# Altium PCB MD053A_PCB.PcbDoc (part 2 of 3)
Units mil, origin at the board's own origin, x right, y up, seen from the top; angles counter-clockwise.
Board outline 3650 x 5180 mil, 4 copper layers (Top Layer, GND Layer, Power Layer, Bottom Layer), stack 58.4 mil thick; 251 components, 138 nets, 532 pads, 1017 vias.
Unrouted connection lines stored in the file: 42.
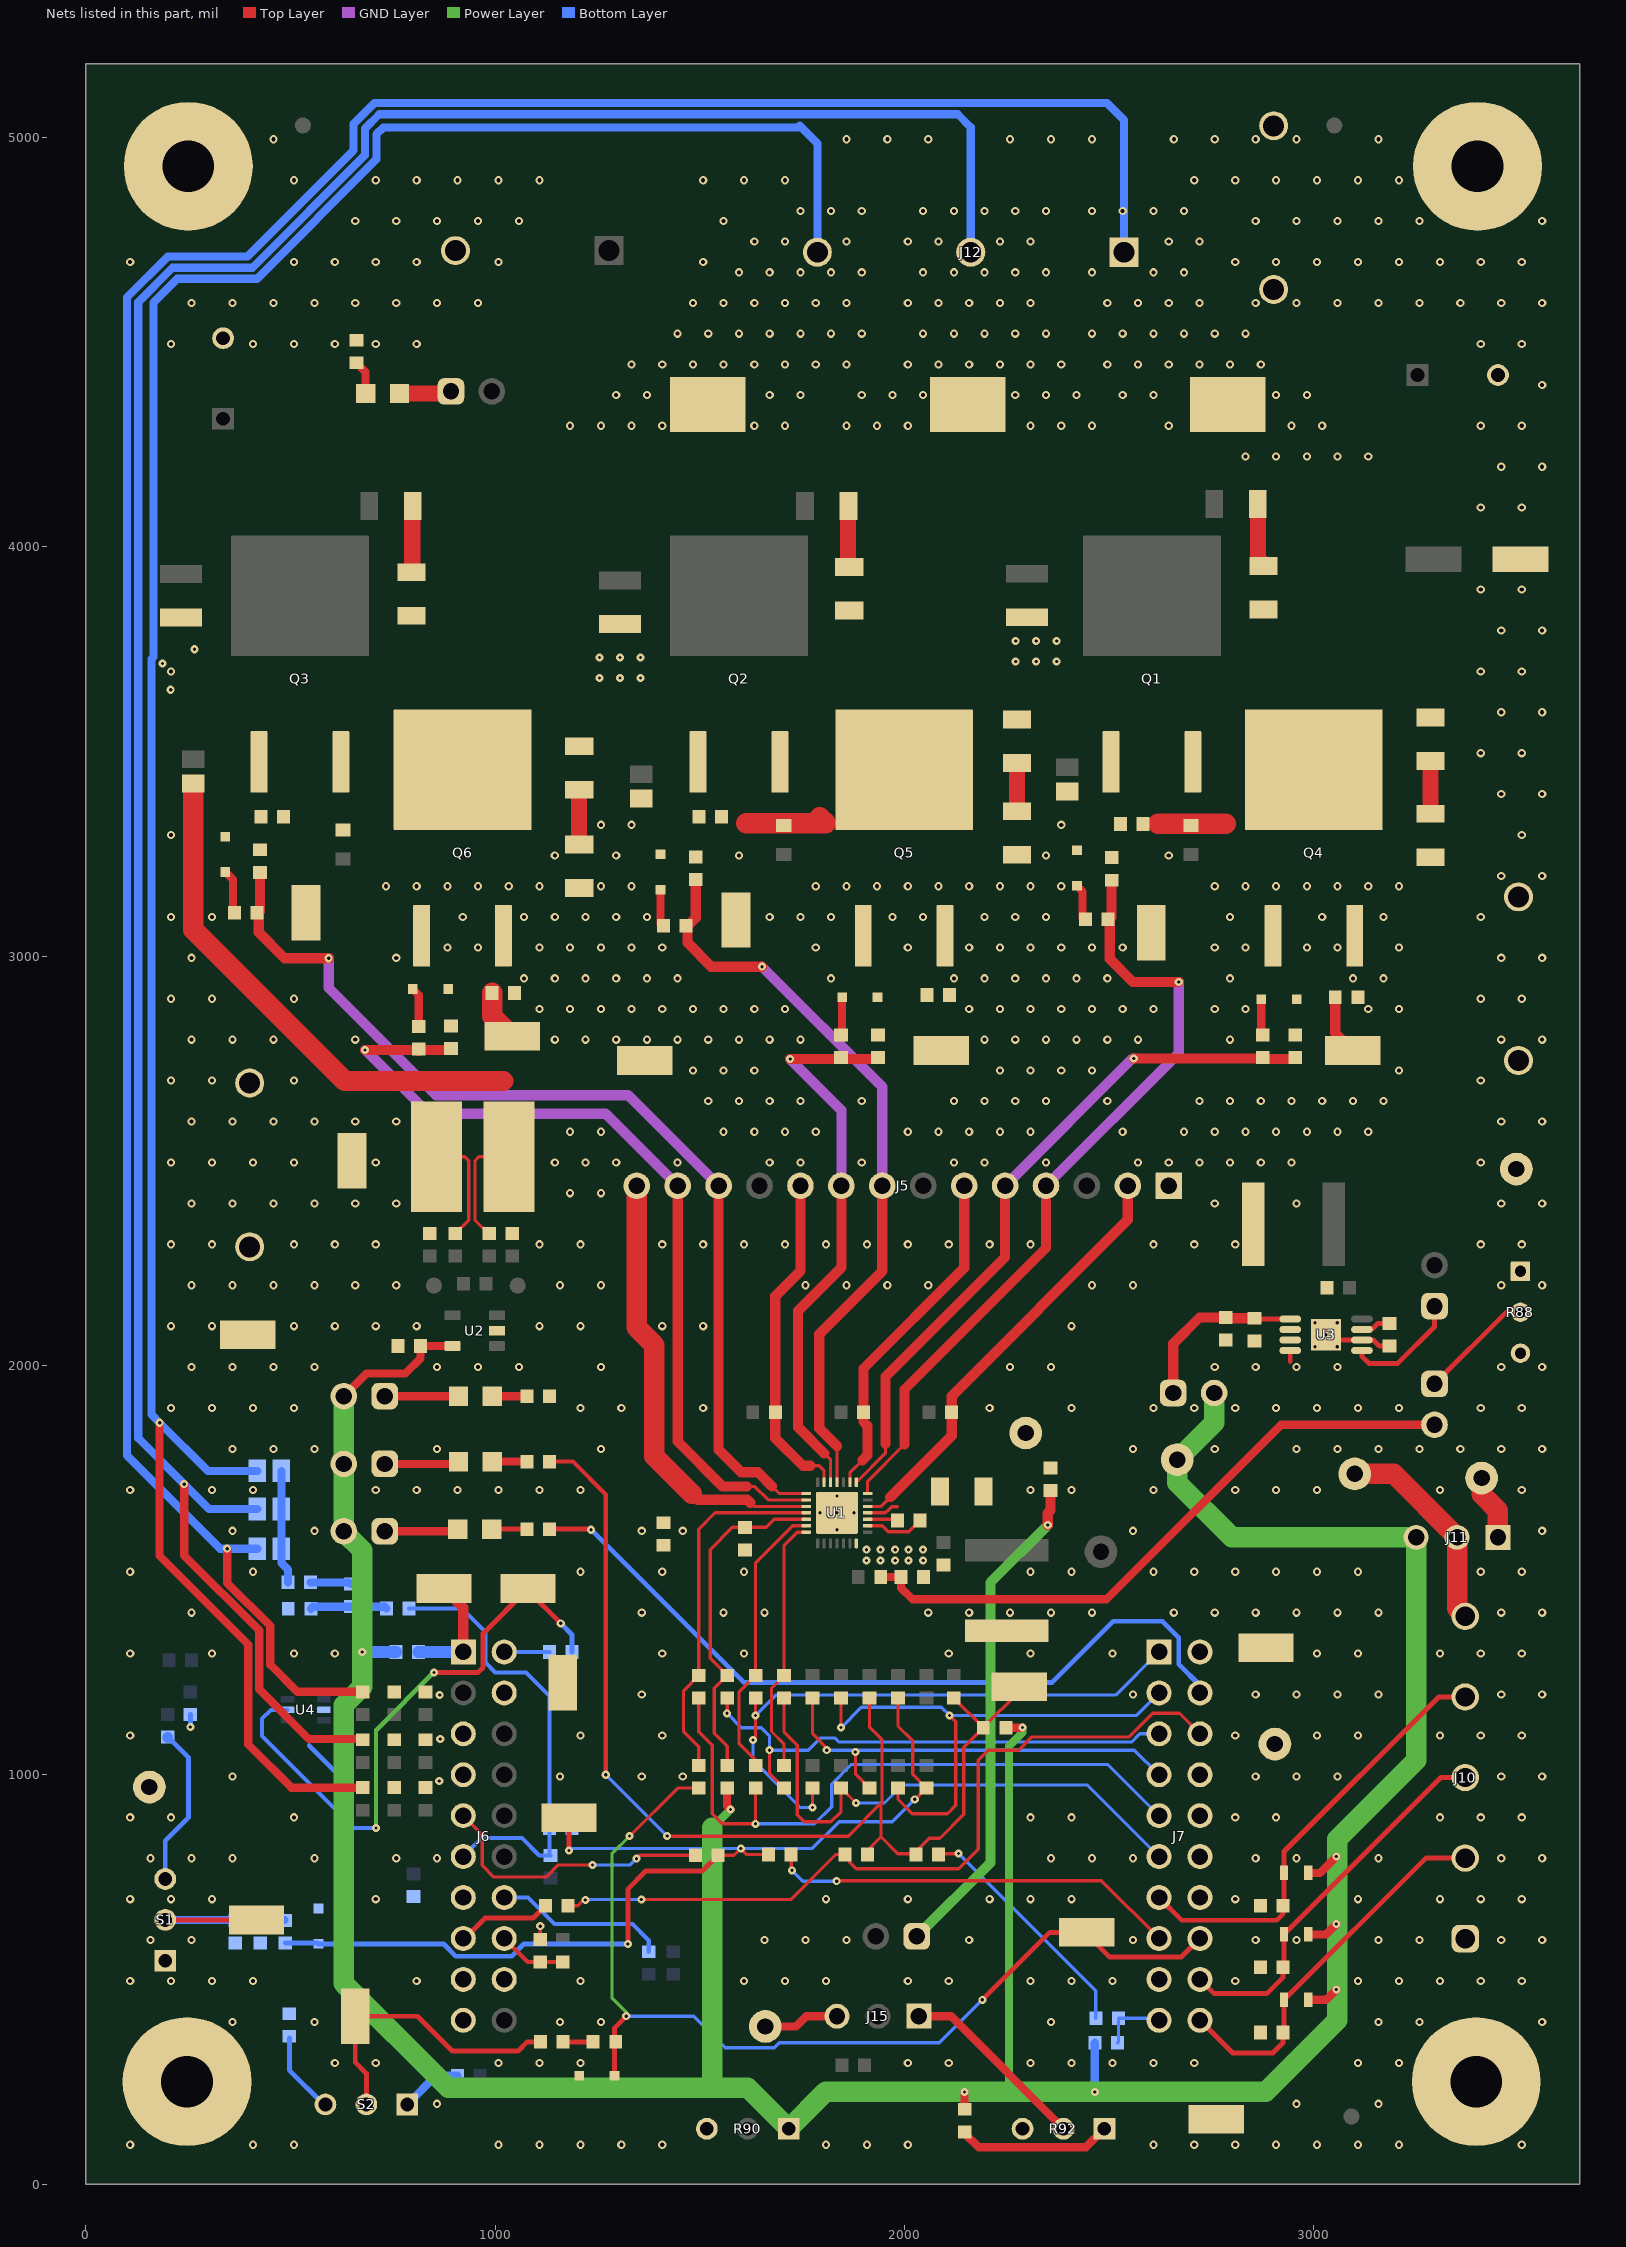
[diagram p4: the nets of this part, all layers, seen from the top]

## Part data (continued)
C6: library part CMP-0007424-3, "CAP, CERM, 0.47 uF, 25 V, +/- 10%, X7R, 0603", Cap_Case=0603, Manufacturer=MuRata, Supplier Part Number 1=490-3291-1-ND, TempCo=X7R, Tolerance_%=10%, Value1=Unknown, Value2=25V, ValueDisplayed=0.47uF
C7: library part CMP-0086153-1, "CAP, CERM, 10 µF, 50 V,+/- 10%, X5R, 1206", Cap_Case=1206, Manufacturer="Taiyo Yuden", TempCo=X5R, Tolerance_%=10%, Value2=50V, ValueDisplayed=10µF
C10 C11 C12 C22 C23 C24: library part CMP-0008756-2, "CAP CER 3900PF 100V X7R 1206", Cap_Case=1206, Manufacturer="AVX Corporation", Supplier Part Number 1=478-6364-1-ND, TempCo=X7R, Tolerance_%=10%, Value1=Unknown, Value2=100V, ValueDisplayed=3900pF
C13 C15 C17 C25 C26 C27 C37: library part CMP-0007441-5, "CAP, CERM, 2000 pF, 50 V, +/- 10%, X7R, 0603", Cap_Case=0603, Manufacturer=MuRata, TempCo=X7R, Tolerance_%=10%, Value1=Unknown, Value2=50V, ValueDisplayed=2000pF
C14 C16 C18: library part CMP-0009084-1, "CAP, CERM, 2.2 uF, 100 V, +/- 10%, X7R, 1210", Cap_Case=1210, Manufacturer=Kemet, Supplier Part Number 1=399-5511-2-ND, TempCo=X7R, Tolerance_%=10%, Value1=Unknown, Value2=100V, ValueDisplayed=2.2uF
C19 C20 C21: library part CMP-0007542-2, "CAP, CERM, 0.01 uF, 100 V, +/- 5%, X7R, 0805", Cap_Case=0805, Manufacturer=AVX, Supplier Part Number 1=478-3745-1-ND, TempCo=X7R, Tolerance_%=5%, Value1="0.078 ohm", Value2=100V, ValueDisplayed=0.01uF
C28 C32: library part CMP-0006740-4, "CAP, CERM, 330 pF, 100 V, +/- 10%, X7R, 0603", Cap_Case=0603, Manufacturer=AVX, Supplier Part Number 1=478-1196-1-ND, TempCo=X7R, Tolerance_%=10%, Value1="0.472 ohm", Value2=100V, ValueDisplayed=330pF
C29: library part CMP-0006857-4, "CAP, CERM, 0.1 uF, 16 V, +/- 5%, X7R, 0603", Cap_Case=0603, Manufacturer=Kemet, Supplier Part Number 1=399-1097-1-ND, TempCo=X7R, Tolerance_%=5%, Value1=Unknown, Value2=16V, ValueDisplayed=0.1uF
C30: library part CMP-0006998-4, "CAP, CERM, 0.01 uF, 50 V, +/- 5%, C0G/NP0, 0603", Cap_Case=0603, Manufacturer=TDK, Supplier Part Number 1=445-14056-1-ND, TempCo=C0G/NP0, Tolerance_%=5%, Value1=Unknown, Value2=50V, ValueDisplayed=0.01uF
C31: library part CMP-0007387-4, "CAP, CERM, 2200 pF, 16 V, +/- 10%, X7R, 0603", Cap_Case=0603, Manufacturer=MuRata, Supplier Part Number 1=GRM188R71C222KA01D-ND, TempCo=X7R, Tolerance_%=10%, Value1=Unknown, Value2=16V, ValueDisplayed=2200pF
C35: library part CMP-0006872-5, "CAP, CERM, 10 uF, 6.3 V, +/- 20%, X5R, 0603", Cap_Case=0603, Manufacturer=Kemet, Supplier Part Number 1=399-5504-1-ND, TempCo=X5R, Tolerance_%=20%, Value1="0.004 ohm", Value2=6.3V, ValueDisplayed=10uF
C36: library part CMP-0007475-4, "CAP, CERM, 2200 pF, 100 V, +/- 10%, X7R, 0603", Cap_Case=0603, Manufacturer=MuRata, Supplier Part Number 1=490-1478-1-ND, TempCo=X7R, Tolerance_%=10%, Value1=Unknown, Value2=100V, ValueDisplayed=2200pF
C38: library part CMP-0011397-2, "CAP, AL, 10 uF, 80 V, +/- 20%, 2.4 ohm, SMD", Cap_Case=F80, Manufacturer=Chemi-Con, Tolerance_%=20%, Value1="2.4 ohm", Value2=80V, ValueDisplayed=10uF
C39 C40: library part CMP-0009875-2, "CAP, AL, 390 uF, 100 V, +/- 20%, 0.026 ohm, TH", Cap_Case=12.5x35mm, Manufacturer=Chemi-Con, Supplier Part Number 1=565-4021-ND, Tolerance_%=20%, Value1="0.026 ohm", Value2=100V, ValueDisplayed=390uF
C41 C45 C46 C47: library part CMP-0083854-1, "CAP, CERM, 0.1 µF, 50 V,+/- 5%, X7R, 0603", Cap_Case=0603, Manufacturer=AVX, TempCo=X7R, Tolerance_%=5%, Value2=50V, ValueDisplayed=0.1µF
C42 C43 C44: library part CMP-0006826-4, "CAP, CERM, 1000 pF, 16 V, +/- 10%, X7R, 0603", Cap_Case=0603, Manufacturer="Wurth Elektronik", Supplier Part Number 1=710-885012206034, TempCo=X7R, Tolerance_%=10%, Value1=Unknown, Value2=16V, ValueDisplayed=1000pF
C48: library part CMP-0006811-4, "CAP, CERM, 10 pF, 10 V, +/- 10%, X7R, 0603", Cap_Case=0603, Manufacturer=AVX, Supplier Part Number 1=0603ZC100KAT2A-ND, TempCo=X7R, Tolerance_%=10%, Value1=Unknown, Value2=10V, ValueDisplayed=10pF
D1 D3: library part CMP-0002888-2, "LED, Green, SMD", Color=Green, Manufacturer=Lite-On, Value1=W, Value2=2V
D2: library part CMP-0002829-3, "LED, Red, SMD", Color=red, Manufacturer=Lite-On, Value1=W, Value2=2V
D4: library part CMP-0002890-1, "LED, Orange, SMD", Color=orange, Manufacturer=Lite-On, Supplier Part Number 1=160-1413-1-ND, Value1=W, Value2=2V
D5 D6 D7 D8 D9 D10: library part CMP-0076911-2, "Diode, Switching, 75 V, 0.25 A, SOD-323", Manufacturer="Micro Commercial Components", Value1=0.25A, Value2=V
D11 D12: library part CMP-0085730-1, "Diode, Zener, 3.3 V, 300 mW, AEC-Q101, SOD-323", Manufacturer="ON Semiconductor", Power_W=300mW, Value1=0.3W
FID1 FID2 FID3: library part CMP-0077181-1, "Fiducial mark.  There is nothing to buy or mount.", Manufacturer=N/A
H1 H2 H3 H4: library part CMP-0003617-1, "Machine Screw, Round, #4-40 x 1/4, Nylon, Philips panhead", Manufacturer="B&F Fastener Supply", Supplier Part Number 1=H542-ND
H5 H6 H7 H8: library part CMP-0003610-1, "Standoff, Hex, 0.5\"L #4-40 Nylon", Manufacturer=Keystone, Supplier Part Number 1=36-1902C-ND
J1 J2 J3 J4 J14: library part CMP-0075405-3, "Header, 100mil, 2x1, Gold, TH", Color=Black, Current_A=6.3A, Manufacturer=Samtec, Supplier Part Number 1=SAM1029-02-ND, Voltage_V=550V
J5: library part CMP-0075428-1, "Header, 100mil, 14x1, Gold, TH", Color=Black, Current_A=6.3A, Manufacturer=Samtec, Supplier Part Number 1=SAM1029-14-ND, Voltage_V=550V
J6 J7: library part CMP-0075613-1, "Receptacle, 2.54mm, 10x2, Gold, TH", Color=Black, Current_A=6.3A, Manufacturer=Samtec, Voltage_V=550V
J8 J13 J16: library part CMP-0075405-3, "Header, 100mil, 2x1, Gold, TH", Color=Black, Current_A=6.3A, Manufacturer=Samtec, PartNumber=TSW-102-07-G-S, Supplier Part Number 1=SAM1029-02-ND, Voltage_V=550V
J9: library part CMP-0055527-1, "Terminal Block, 9.52mm, 2x1, R/A, TH", Color=Green, Current_A=32A, Manufacturer="Phoenix Contact", PartNumber=1902547, Supplier Part Number 1=277-5951-ND, Voltage_V=1kV
J10: library part CMP-0055532-1, "Terminal Block, 5mm, 5x1, R/A, TH", Color=Green, Current_A=16A, Manufacturer="Phoenix Contact", PartNumber=1792892, Supplier Part Number 1=277-2521-ND, Voltage_V=400V
J11 J15: library part CMP-0065026-1, "Header, 2.54mm, 3x1, Tin, TH", Color=Black, Current_A=3A, Manufacturer=FCI, PartNumber=68001-403HLF, Supplier Part Number 1=609-3471-ND, Voltage_V=1.5kV
J12: library part CMP-0055528-1, "Terminal Block, 9.52mm, 3x1, R/A, TH", Color=Green, Current_A=32A, Manufacturer="Phoenix Contact", PartNumber=1904150, Supplier Part Number 1=277-6184-ND, Voltage_V=1kV
LBL1: library part CMP-0003625-1, "Thermal Transfer Printable Labels, 0.650\" W x 0.200\" H - 10,000 per roll", Manufacturer=Brady, Supplier Part Number 1=97C5133
Logo1: library part CMP-0074844-1
Logo2: library part CMP-0074838-1, "Texas Instrument Corporate Signature"
Logo3: library part CMP-0074847-1, "FCC_disclaimer"
Logo4: library part CMP-0074769-1
LOGO5 LOGO6 LOGO7: library part CMP-0074837-1, "IEC 61010-1 Hot Surface Warning"
NT1 NT2 NT3: library part CMP-0078142-2, "Single point connection between nets.", Manufacturer=N/A
Q1 Q2 Q3 Q4 Q5 Q6: library part CMP-0092295-1, "MOSFET 60-V, N channel NexFET power MOSFET, single D2PAK, 1.6 mOhm 3-DDPAK/TO-263 -55 to 175", Digikey Part Number=296-44122-1-ND, Drain To Source Breakdown Voltage=60V, Input Capacitace At Vds="8790pF @ 30V", Manufacturer="Texas Instruments", Mouser Part Number=595-CSD18536KTTT, Operating Temperature Range="-55°C to +175°C", Power_W=375W, Pulse Drain Current=400A, Typ Forward Diode Voltage=0.9V
R1 R2 R3 R4 R5 R6 R7 R8 R9 R10 R11 R12 R13 R14 R15 R17 R18 R19 R20 R21 R26 R27 R28 R29 R30 R31 R32 R33 R34 R35 R36 R38 R39 R58 R61 R75 R76 R80 R81 R85: library part CMP-0025874-4, "RES, 0, 5%, 0.1 W, AEC-Q200 Grade 0, 0603", Manufacturer=Panasonic, Power_W=100mW, Supplier Part Number 1=P0.0GCT-ND, TempCo="600 ppm/C", Tolerance_%=5%, Value2=0.1W, Value_Code=0000, ValueDisplayed=0
R16: library part CMP-0025830-4, "RES, 5.1 k, 5%, 0.1 W, AEC-Q200 Grade 0, 0603", Manufacturer=Vishay-Dale, Power_W=100mW, Supplier Part Number 1=541-5.1KGCT-ND, TempCo="200 ppm/C", Tolerance_%=5%, Value2=0.1W, Value_Code=5k10, ValueDisplayed=5.1k
R22 R23 R25: library part CMP-0025941-5, "RES, 820, 5%, 0.1 W, 0603", Manufacturer=Yageo, Power_W=100mW, Supplier Part Number 1=311-820GRCT-ND, TempCo="100 ppm/C", Tolerance_%=5%, Value2=0.1W, Value_Code=820R, ValueDisplayed=820
R24: library part CMP-0023463-3, "RES, 2.00 k, 0.1%, 0.1 W, 0603", Manufacturer="Susumu Co Ltd", Power_W=100mW, Supplier Part Number 1=RG16P2.0KBCT-ND, TempCo="25 ppm/C", Tolerance_%=0.1%, Value2=0.1W, Value_Code=2k00, ValueDisplayed=2.00k
R37: library part CMP-0025701-2, "RES, 10 k, 5%, 0.1 W, 0603", Manufacturer=Vishay-Dale, Power_W=100mW, Supplier Part Number 1=541-10KGCT-ND, TempCo="200 ppm/C", Tolerance_%=5%, Value2=0.1W, Value_Code=10k0, ValueDisplayed=10k
R40 R41 R42 R55 R56 R57: library part CMP-0016763-3, "RES, 1.50, 1%, 0.25 W, AEC-Q200 Grade 0, 1206", Manufacturer=Vishay-Dale, Power_W=250mW, Supplier Part Number 1=53K1888, TempCo="100 ppm/C", Tolerance_%=1%, Value2=0.25W, Value_Code=1R50, ValueDisplayed=1.50
R43 R44 R45 R46 R47 R48 R49 R50 R51 R52 R53 R54: library part CMP-0025703-4, "RES, 10, 5%, 0.1 W, AEC-Q200 Grade 0, 0603", Manufacturer=Vishay-Dale, Power_W=100mW, Supplier Part Number 1=541-10GCT-ND, TempCo="200 ppm/C", Tolerance_%=5%, Value2=0.1W, Value_Code=10R0, ValueDisplayed=10
R59: library part CMP-0025829-4, "RES, 56, 5%, 0.1 W, AEC-Q200 Grade 0, 0603", Manufacturer=Vishay-Dale, Power_W=100mW, Supplier Part Number 1=541-56GCT-ND, TempCo="200 ppm/C", Tolerance_%=5%, Value2=0.1W, Value_Code=56R0, ValueDisplayed=56
R60: library part CMP-0015025-2, "RES, 0.001, 1%, 4 W, RES_2725", Manufacturer="Stackpole Electronics Inc", Power_W=4W, Supplier Part Number 1=CSS2725FT1L00CT-ND, TempCo="50 ppm/C", Tolerance_%=1%, Value_Code=1L000, ValueDisplayed=0.001
R62 R63 R64: library part CMP-0025686-1, "RES, 10.0 k, 0.1%, 0.1 W, AEC-Q200 Grade 1, 0603", Manufacturer=Vishay-Dale, Power_W=100mW, Supplier Part Number 1=TNP10.0KAACT-ND, TempCo="25 ppm/C", Tolerance_%=0.1%, Value2=0.1W, Value_Code=10k0, ValueDisplayed=10.0k
R65 R67 R68 R69 R83: library part CMP-0022008-4, "RES, 110 k, 1%, 0.1 W, AEC-Q200 Grade 0, 0603", Manufacturer=Vishay-Dale, Power_W=100mW, Supplier Part Number 1=541-110KHCT-ND, TempCo="100 ppm/C", Tolerance_%=1%, Value2=0.1W, Value_Code=110k
R66 R70 R71 R72 R86: library part CMP-0022458-4, "RES, 4.99 k, 1%, 0.1 W, AEC-Q200 Grade 0, 0603", Manufacturer=Vishay-Dale, Power_W=100mW, Supplier Part Number 1=541-4.99KHCT-ND, TempCo="100 ppm/C", Tolerance_%=1%, Value2=0.1W, Value_Code=4k99, ValueDisplayed=4.99k
R73 R74 R77: library part CMP-0086251-1, "RES, 10.0 k, 0.05%, 0.1 W, AEC-Q200 Grade 0, 0603", Manufacturer=Panasonic, Power_W=100mW, TempCo="10 ppm/C", Tolerance_%=0.05%, Value2=0.1W, Value_Code=10k0, ValueDisplayed=10.0k
R78 R82 R84: library part CMP-0019089-2, "RES, 1.00 k, 0.1%, 0.25 W, 0805", Manufacturer="TE Connectivity", Power_W=250mW, Supplier Part Number 1=A110543CT-ND, TempCo="25 ppm/C", Tolerance_%=0.1%, Value2=0.25W, Value_Code=1k00, ValueDisplayed=1.00k
R87: library part CMP-0025698-4, "RES, 100 k, 5%, 0.1 W, AEC-Q200 Grade 0, 0603", Manufacturer=Vishay-Dale, Power_W=100mW, Supplier Part Number 1=541-100KGCT-ND, TempCo="200 ppm/C", Tolerance_%=5%, Value2=0.1W, Value_Code=100k
R88: library part CMP-0088033-1, "500 kOhms 0.5W, 1/2W PC Pins Through Hole Trimmer Potentiometer Cermet 25 Turn Top Adjustment", Manufacturer=Bourns, Power_W=500mW, TempCo=100ppm/°C, Tolerance_%=10%
R89: library part CMP-0025940-5, "RES, 7.5 k, 5%, 0.1 W, 0603", Manufacturer=Yageo, Power_W=100mW, Supplier Part Number 1=311-7.5KGRCT-ND, TempCo="100 ppm/C", Tolerance_%=5%, Value2=0.1W, Value_Code=7k50, ValueDisplayed=7.5k
R90 R92: library part CMP-0001776-2, "Trimmer Potentiometer, 25kohm, 0.5W, TH", Manufacturer=Bourns, Supplier Part Number 1=3352T-253LF-ND
R91: library part CMP-0025701-3, "RES, 10 k, 5%, 0.1 W, 0603", Manufacturer=Vishay-Dale, Power_W=100mW, Supplier Part Number 1=541-10KGCT-ND, TempCo="200 ppm/C", Tolerance_%=5%, Value2=0.1W, Value_Code=10k0, ValueDisplayed=10k
S1 S2: library part CMP-0002155-2, "SWITCH TOGGLE SPDT 0.4VA 28V", CurrentRating_mA=100A, Manufacturer="NKK Switches", PartNumber=B12AP, Supplier Part Number 1=360-1012-ND
SH-J1 SH-J2 SH-J3 SH-J4 SH-J5 SH-J6 SH-J7 SH-J8 SH-J9: library part CMP-0003623-3, "Shunt, 100mil, Gold plated, Black", Alternate Manufacturer=3M, Alternate PartNumber=969102-0000-DA, Manufacturer=Samtec, Supplier Part Number 1=SAM8858-ND
TP1 TP2 TP3 TP4 TP5 TP6 TP7 TP9 TP10 TP13 TP14 TP15 TP16 TP17 TP18 TP19 TP20 TP23 TP24: library part CMP-0055152-1, "Test Point, Miniature, SMT", Manufacturer=Keystone, PartNumber=5015, Supplier Part Number 1=36-5015TR-ND
TP8 TP11 TP12 TP21 TP30 TP31: library part CMP-0055137-1, "Test Point, Miniature, Red, TH", Color=Red, Manufacturer=Keystone, PartNumber=5000, Supplier Part Number 1=36-5000-ND
TP22 TP28 TP29: library part CMP-0055138-1, "Test Point, Miniature, Black, TH", Color=Black, Manufacturer=Keystone, PartNumber=5001, Supplier Part Number 1=36-5001-ND
TP25 TP26 TP27: library part CMP-0075110-1, "1mm Uninsulated Shorting Plug, 10.16mm spacing, TH", Manufacturer=Harwin, PartNumber=D3082-05, Supplier Part Number 1=952-1873-ND
TP32 TP33: library part CMP-0003825-1, "1mm Test Point, SMT", Manufacturer=Any, PartNumber=TP_SM_1MM
TP34 TP35 TP36: library part CMP-0055153-1, "Test Point, Compact, SMT", Manufacturer=Keystone, PartNumber=5016, Supplier Part Number 1=36-5016TR-ND
U1: library part CMP-0091885-1, "Three-Phase BLDC Gate Driver", Manufacturer="Texas Instruments", Max Supply Voltage=60V, Min Supply Voltage=4.5V, Nominal Supply Current=4-5mA, Operating Temperature Range="-40°C to +150°C", Switching Frequency=200kHz
U2: library part CMP-0013067-2, "Low- and High-Side Measurement, Multichannel, Voltage Output, Current-Sense Amplifier, DBV0005A (SOT-5)", Alternate Manufacturer="Texas Instruments", Alternate PartNumber=INA180A1IDBVT
U3: library part CMP-0066910-3, "Automotive 60V, 5uA IQ Low-Dropout 100mA Linear Regulator with Enable and Power Good, DGN0008B (VSSOP-8)", Alternate Manufacturer="Texas Instruments"
U4: library part CMP-0043118-3, "4-Channel ESD Solution for High-Speed Differential Interface, DCK0006A (SOT-SC70-6)", Breakdown Voltage(Min)(V)=9, Differential Capacitance(pF)=0.05, IO Capacitance(Typ)(pF)=0.8, IO Leakage Current(nA)=10, Manufacturer="Texas Instruments", Operating Temperature Range="-40 to 85 C", Rating=Catalog
ZZ1: library part CMP-0003616-3
ZZ2: library part CMP-0077236-1
ZZ3: library part CMP-0077237-1
ZZ4: library part CMP-0077238-1

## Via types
v1: diameter 20, hole 10, Top Layer to Bottom Layer, tented both sides, 759 vias
v2: diameter 19.68, hole 7.87, Top Layer to Bottom Layer, tented both sides, 248 vias
v3: diameter 19.68, hole 7.87, Top Layer to Bottom Layer, 10 vias

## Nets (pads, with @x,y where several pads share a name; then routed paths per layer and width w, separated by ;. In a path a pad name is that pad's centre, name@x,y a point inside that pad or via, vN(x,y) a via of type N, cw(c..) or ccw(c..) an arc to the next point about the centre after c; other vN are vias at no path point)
3V3_MCU: J6.1 R29.2 TP13.1 | length 283.7
  Top Layer w25: TP13.1@875,1455 921.85,1408.15 J6.1@921.85,1300
  Bottom Layer w30: R29.2@812.56,1300 J6.1@921.85,1300
+5V: R30.2 TP14.1 U4.5 | length 1486.9
  Top Layer w12: v2(850,1250) 958.15,1250 970.24,1262.08 970.24,1345.24 TP14.1@1080,1455 1080,1450 v2(1160,1370)
  Power Layer w10: v2(708.54,870) 708.54,1108.54 710,1110
  Power Layer w12: 710,1110 v2(850,1250)
  Bottom Layer w10: U4.5@492.56,1158.5 451.59,1158.5 430,1136.91 430,1095 655,870 v2(708.54,870)
  Bottom Layer w12: v2(1160,1370) 1187.56,1342.44 R30.2@1187.56,1300
AVDD: C29.1 J1.2 J2.2 J4.2 J11.3 J16.2 R4.1 R16.1 R29.1 R36.1 R62.2 R63.2 R64.2 R89.2 R90.1 TP8.1 U2.5 | length 8830
  Top Layer w20: J1.2@630,1925 685,1980 780,1980 817.56,2017.56 C29.1@817.56,2047.6 U2.5@895.87,2047.6 ; R4.1@1566.52,967.44 1566.52,923.48 v2(1575,915) ; R89.2@2146.85,186.5 v2(2146.85,225) ; R16.1@2247.56,1115 2287.81,1115 v2(2288.35,1115.53) ; R64.2@2986.38,450 3030,450 v2(3055,475) ; R63.2@2986.38,610 3030,610 v2(3055,635) ; R62.2@2986.38,760 3015,760 v2(3055,800)
  Power Layer w20: 985,235 985.12,235 ; 1530,870 v2(1575,915) ; 2255,225 2255,1070 2288.35,1103.35 v2(2288.35,1115.53)
  Power Layer w50: J1.2@630,1925 J2.2@630,1759.41 J4.2@630,1595 630,1593.06 675,1548.06 v2(675,1300) 675,1215 630,1170 630,490 885,235 985,235 ; 985.12,235 1530,235 ; 1530,870 1530,235 ; J16.2@2756.37,1932.76 2756.37,1859.93 TP8.1@2666.44,1770 2666.44,1713.56 2800,1580 J11.3@3250,1580 3250,1035 3057.17,842.17 3057.17,400 2882.17,225 v2(2465,225) 2255,225 v2(2146.85,225) 1806.93,225 R90.1@1716.93,135 1616.93,235 1530,235
  Bottom Layer w20: v2(2465,225) 2465,344.29 R36.1@2465.71,345
  Bottom Layer w30: v2(675,1300) R29.1@757.44,1300
BSTA: C3.1 J5.2 U1.5 | length 1065.8
  Top Layer w7.87: U1.5@1909.8,1655.75 1942.63,1655.75 1965.32,1678.44
  Top Layer w25: 1965.32,1678.44 2115.12,1828.24 C3.1@2115.12,1885.43 2115.12,1925.12 2545.67,2355.67 J5.2@2545.67,2438.91
BSTB: C8.1 J5.6 U1.9 | length 847.7
  Top Layer w7.87: U1.9@1866.5,1714.8 1866.5,1737.78 1897.27,1768.55
  Top Layer w25: 1897.27,1768.55 1909.37,1780.65 1909.37,1853.14 1899.72,1862.8 C8.1@1899.72,1885.43 1899.72,1992.58 2145.67,2238.54 J5.6@2145.67,2438.91
BSTC: C9.1 J5.10 U1.13 | length 821.7
  Top Layer w7.87: 1770,1755 1791.54,1755 1803.5,1743.03 U1.13@1803.5,1714.8
  Top Layer w25: C9.1@1684.32,1885 1684.32,1822.47 1751.79,1755 1770,1755 ; C9.1@1684.32,1885.43 1684.32,2169.32 1745.67,2230.67 J5.10@1745.67,2438.91
CPH: C6.1 U1.3 | length 73.9
  Top Layer w7.87: U1.3@1909.8,1624.25 1979.5,1624.25 C6.1@1982.44,1621.31
CPL: C6.2 U1.2 | length 145.4
  Top Layer w7.87: U1.2@1909.8,1608.5 1945.21,1608.5
  Top Layer w8: 1945.21,1608.5 1960.14,1593.58 2009.83,1593.58 C6.2@2037.56,1621.31
CTAP: C48.1 J6.11 R32.2 R85.2 | length 1115.9
  Bottom Layer w10: R85.2@789.41,1406.31 918.69,1406.31 975.85,1349.15 975.85,1274.15 1000,1250 1075,1250 1132.44,1192.56 C48.1@1132.44,870 1132.44,805.12 R32.2@1135,802.56 1107.44,802.56 1065,845 966.85,845 J6.11@921.85,800
DRVOFF: D12.1 J7.16 R6.1 R37.1 TP1.1 | length 2447.4
  Top Layer w8: D12.1@1291.75,264.71 D12.1@1294.37,267.55 ; v2(1328,850) 1445.44,967.44 R6.1@1496.93,967.44
  Top Layer w12: D12.1@1291.75,264.71 1291.75,344.55 1291.52,381.52 v2(1320,410) ; v2(2190,450) 2355,615 TP1.1@2445,615 2445,610.5 2500.5,555 2676.85,555 J7.16@2721.85,600
  Power Layer w8: v2(1320,410) 1320,420 1285,455 1285,807 v2(1328,850)
  Bottom Layer w8: v2(1320,410) 1485,410 1561.87,333.13 1681.49,333.13 1693.36,345 2085,345 v2(2190,450)
DRVOFF_SW: R76.1 S2.2 TP24.1 | length 724.2
  Top Layer w12: S2.2@685,194.37 685,270 657.85,297.15 TP24.1@657.85,410 810,410 895,325 1055.85,325 1078.25,347.4 R76.1@1110.71,347.4
DT: J14.2 R20.1 R91.2 | length 1562.3
  Top Layer w20: R20.1@1942.03,1483.21 R91.2@1986.2,1483.21 ; R91.2@1991.5,1483.21 1991.5,1456.65 2019.35,1428.8 2493.8,1428.8 2920,1855 J14.2@3295,1855
GHA: J5.4 R43.1 R46.1 U1.7 | length 1946.5
  Top Layer w7.87: U1.7@1909.8,1687.24 1909.8,1717.18 2000,1807.37
  Top Layer w25: 2000,1807.37 2000,1941.39 2345.67,2287.06 J5.4@2345.67,2438.91 ; R43.1@2505.94,3181.69 2505.94,3094.45 2501.5,3090 2501.5,2993.5 2558.19,2936.81 v2(2670,2936.81)
  GND Layer w25: J5.4@2345.67,2438.91 2670,2763.24 v2(2670,2936.81)
GHA_FET: C13.1 D5.2 Q1.1 R43.2 TP15.1
GHB: J5.8 R44.1 R47.1 U1.11 | length 1828.8
  Top Layer w7.87: U1.11@1835,1714.8 1835,1802.61 1835.3,1802.9
  Top Layer w25: R44.1@1490,3183.5 1490,3094.18 1469.95,3074.13 1469.95,3032.41 1527.89,2974.47 v2(1651.87,2974.47) ; 1835.3,1802.9 1791.54,1846.67 1791.54,2076.44 1945.67,2230.58 J5.8@1945.67,2438.91
  GND Layer w25: v2(1651.87,2974.47) 1945.67,2680.67 J5.8@1945.67,2438.91
GHB_FET: C15.1 D6.2 Q2.1 R44.2 TP16.1
GHC: J5.12 R45.1 R48.1 U1.15 | length 2470.5
  Top Layer w7.87: 1675.97,1705 1693.73,1687.24 U1.15@1760.2,1687.24
  Top Layer w25: R45.1@425,3201.02 425,3109.47 421.92,3106.39 421.92,3058.08 485,2995 v2(592.9,2995) ; J5.12@1545.67,2438.91 1545.67,1794.33 1600.98,1739.02 1641.95,1739.02 1675.97,1705
  GND Layer w25: v2(592.9,2995) 592.9,2922.34 855.24,2660 1324.58,2660 J5.12@1545.67,2438.91
GHC_FET: C17.1 D7.2 Q3.1 R45.2 TP17.1
GLA: J5.5 R49.1 R52.1 U1.8 | length 1713.7
  Top Layer w7.87: U1.8@1882.24,1714.8 1882.6,1714.8 1953.41,1785.62 1953.41,1808.01
  Top Layer w25: 1953.41,1808.01 1953.41,1972.85 2245.67,2265.11 J5.5@2245.67,2438.91 ; v2(2560,2750) 2873.5,2750 2875,2748.5 R49.1@2955,2748.5
  GND Layer w25: J5.5@2245.67,2438.91 2556.76,2750 v2(2560,2750)
GLA_FET: C25.1 D8.2 Q4.1 R49.2 TP18.1 | length 148
  Top Layer w25: C25.1@3052.44,2900 3052.44,2812.18 TP18.1@3095,2769.62
GLB: J5.9 R50.1 R53.1 U1.12 | length 1376.6
  Top Layer w7.87: 1803.66,1785 1819.25,1769.41 U1.12@1819.25,1714.8
  Top Layer w25: v2(1720.5,2748.5) R50.1@1935,2748.5 ; 1803.66,1785 1740,1848.66 1740,2133.46 1845.67,2239.14 J5.9@1845.67,2438.91
  GND Layer w25: v2(1720.5,2748.5) 1845.67,2623.34 J5.9@1845.67,2438.91
GLB_FET: C26.1 D9.2 Q5.1 R50.2 TP19.1
GLC: J5.13 R51.1 R54.1 U1.16 | length 2110.7
  Top Layer w7.87: 1614.31,1704 1634.43,1704 1666.93,1671.5 U1.16@1760.2,1671.5
  Top Layer w25: v2(682,2771) 810.41,2771 812.41,2769 813.96,2770.55 R51.1@891.77,2770.55 ; J5.13@1445.67,2438.91 1445.67,1814.33 1556,1704 1614.31,1704
  GND Layer w25: v2(682,2771) 838,2615 1269.58,2615 J5.13@1445.67,2438.91
GLC_FET: C27.1 D10.2 Q6.1 R51.2 TP20.1 | length 126.7
  Top Layer w50: C27.1@992.17,2910.32 992.17,2853.23 TP20.1@1041.38,2804.02
GND: C1.1 C2.2 C4.2 C5.2 C7.2 C14.2 C16.2 C18.2 C28.1 C29.2 C31.2 C32.2 C33.2 C34.2 C35.2 C36.2 C37.2 C38.2 C39.2 C40.2 C41.2 C42.2 C43.2 C44.2 C45.1 C46.2 C47.2 C48.2 D11.2 D12.2 J5.1 J6.4 J7.2 J9.2 J10.1 R22.1 R24.1 R60.1 R61.2 R66.1 R70.1 R71.1 R72.1 R77.1 R80.1 R86.1 R88.1 R90.3 R91.1 R92.3 TP5.1 TP6.1 TP7.1 TP9.1 TP10.1 TP22.1 TP25.1 TP25.2 TP26.1 TP26.2 TP27.1 TP27.2 TP28.1 TP29.1 U1.28 U1.29 U2.2 U3.4 U3.6 U3.9 U4.2 | length 616
  Top Layer w7.87: R60.1@856.42,2510 925,2510 935,2500 935,2354.96 R61.2@902.6,2322.56 ; C31.2@1110,597.56 v2(1110,630)
  Top Layer w12: 2942.4,2009.97 U3.4@2942.4,2036.61 ; v3(3030,2075) 3042.8,2062.2 U3.6@3117.6,2062.2 3145.24,2062.2 3160,2047.44 C37.2@3185,2047.44
  Bottom Layer w12: v2(255,1116.81) R66.1@255,1147.44 ; 545.5,1071 606.5,1010
  other v1: 108,96 408,96 508,96 1008,96 1108,96 1208,96 1308,96 1408,96 1808,96 1908,96 2008,96 2608,96 2708,96 2808,96 2908,96 3008,96 3108,96 3208,96 3508,96 858,196 2958,196 3158,196 608,296 708,296 1008,296 1108,296 1208,296 2008,296 2108,296 2308,296 2408,296 2508,296 2608,296 2708,296 3108,296 3208,296 358,396 558,396 1158,396 1258,396 2358,396 3158,396 3258,396 3558,396 108,496 208,496 308,496 408,496 808,496 1208,496 1608,496 1708,496 1808,496 2008,496 2108,496 2308,496 2408,496 2508,496 2808,496 3108,496 3208,496 3308,496 3408,496 3508,496 158,596 258,596 1658,596 1758,596 1858,596 2158,596 2558,596 2858,596 2958,596 3158,596 3258,596 3458,596 3558,596 108,696 208,696 308,696 708,696 1808,696 2008,696 2208,696 2308,696 2408,696 2808,696 3108,696 3308,696 3408,696 3508,696 158,796 258,796 358,796 558,796 758,796 858,796 2358,796 2458,796 2558,796 2858,796 2958,796 3158,796 3458,796 3558,796 108,896 208,896 508,896 2308,896 2408,896 2808,896 2908,896 3308,896 3408,896 3508,896 358,996 1158,996 1358,996 1458,996 2858,996 2958,996 3058,996 3458,996 3558,996 108,1096 1208,1096 1408,1096 2808,1096 3008,1096 3108,1096 3308,1096 3408,1096 3508,1096 1358,1196 2558,1196 2858,1196 2958,1196 3058,1196 3158,1196 3458,1196 3558,1196 108,1296 308,1296 508,1296 608,1296 1408,1296 1608,1296 2108,1296 2308,1296 2508,1296 3008,1296 3108,1296 3308,1296 3408,1296 3508,1296 258,1396 1358,1396 1558,1396 1658,1396 2058,1396 2158,1396 2258,1396 2358,1396 2458,1396 2658,1396 2758,1396 2858,1396 2958,1396 3058,1396 3158,1396 3458,1396 3558,1396 108,1496 408,1496 1208,1496 1408,1496 1608,1496 2308,1496 2408,1496 2608,1496 2708,1496 2808,1496 2908,1496 3008,1496 3108,1496 3408,1496 3508,1496 358,1596 558,1596 1358,1596 1458,1596 2558,1596 3558,1596 108,1696 308,1696 408,1696 708,1696 808,1696 908,1696 1008,1696 1108,1696 1208,1696 2308,1696 2408,1696 2608,1696 2808,1696 2908,1696 3008,1696 3308,1696 3508,1696 358,1796 458,1796 558,1796 858,1796 1258,1796 2558,1796 2758,1796 2958,1796 3058,1796 3158,1796 3258,1796 3358,1796 3458,1796 3558,1796 208,1896 308,1896 408,1896 508,1896 1208,1896 1308,1896 1508,1896 2208,1896 2408,1896 2608,1896 2708,1896 2808,1896 2908,1896 3008,1896 3108,1896 3208,1896 3408,1896 3508,1896 258,1996 358,1996 458,1996 558,1996 858,1996 958,1996 1058,1996 1258,1996 2258,1996 2358,1996 2758,1996 2858,1996 2958,1996 3058,1996 3458,1996 3558,1996 208,2096 308,2096 508,2096 608,2096 708,2096 808,2096 1108,2096 1208,2096 1408,2096 1508,2096 2408,2096 258,2196 358,2196 458,2196 558,2196 658,2196 758,2196 1158,2196 1258,2196 1758,2196 1858,2196 1958,2196 2058,2196 2458,2196 2558,2196 3458,2196 3558,2196 208,2296 308,2296 508,2296 608,2296 708,2296 1108,2296 1208,2296 1408,2296 1508,2296 1608,2296 1708,2296 1808,2296 1908,2296 2008,2296 2108,2296 2208,2296 2308,2296 2608,2296 2708,2296 2808,2296 3408,2296 3508,2296 258,2396 358,2396 458,2396 558,2396 658,2396 758,2396 2758,2396 2958,2396 3458,2396 3558,2396 208,2496 308,2496 408,2496 508,2496 708,2496 3408,2496 258,2596 358,2596 458,2596 558,2596 658,2596 758,2596 3458,2596 3558,2596 208,2696 308,2696 508,2696 3408,2696 258,2796 358,2796 458,2796 658,2796 3458,2796 3558,2796 208,2896 308,2896 508,2896 3408,2896 3508,2896 258,2996 758,2996 3458,2996 3558,2996 208,3096 308,3096 3408,3096 3458,3196 3558,3196 208,3296 3508,3296 3458,3396 3558,3396 3408,3496 3508,3496 3458,3596 3558,3596 208,3696 3408,3696 3508,3696 3458,3796 3558,3796 3408,3896 3508,3896 3408,4096 3508,4096 3458,4196 3558,4196 3408,4296 3508,4296 3558,4396 208,4496 408,4496 508,4496 608,4496 708,4496 808,4496 3408,4496 3508,4496 258,4596 358,4596 458,4596 558,4596 658,4596 758,4596 858,4596 958,4596 2858,4596 2958,4596 3058,4596 3158,4596 3258,4596 3358,4596 3458,4596 3558,4596 108,4696 508,4696 608,4696 708,4696 808,4696 1008,4696 1508,4696 2808,4696 2908,4696 3008,4696 3108,4696 3208,4696 3308,4696 3408,4696 3508,4696 658,4796 758,4796 858,4796 958,4796 1058,4796 1558,4796 2858,4796 2958,4796 3058,4796 3158,4796 3258,4796 3558,4796 508,4896 708,4896 808,4896 908,4896 1008,4896 1108,4896 1508,4896 1608,4896 1708,4896 2708,4896 2808,4896 2908,4896 3008,4896 3108,4896 3208,4896 458,4996 1858,4996 1958,4996 2058,4996 2258,4996 2358,4996 2458,4996 2658,4996 2758,4996 2858,4996 2958,4996 3158,4996
  other v2: 863.15,985 865.54,1087.56 864.2,1195 1907.06,1523.58 1941.09,1523.58 1977.08,1523.58 2010,1523.58 2045.5,1523.58 1907.06,1550 1941.09,1550 1977.08,1550 2010,1550 2045,1550 207,3651 1255,3680 1305,3680 1355,3680 187,3715 2271.66,3720 2321.66,3720 2371.66,3720 1255,3730 1305,3730 1355,3730 265,3750 2271.66,3770 2321.66,3770 2371.66,3770
  other v3: 1835,1598.66 1793.66,1640 1835,1640 1876.34,1640 1835,1681.34 3002.83,2045.87 3057.17,2045.87 3002.83,2104.13 3057.17,2104.13
GVDD: C7.1 R87.1 TP12.1 U1.4 | length 79
  Top Layer w7.87: U1.4@1909.8,1640 1953.18,1640 1962.16,1648.98 1962.69,1648.98 1968.71,1655 1982.54,1655
HALL_PWR: J10.5 J11.2 TP21.1 | length 515.6
  Top Layer w50: TP21.1@3100,1735 3195,1735 J11.2@3350,1580 3350,1406.85 J10.5@3370,1386.85
HALLA: C42.1 J7.13 J10.4 R62.1 | length 1085.1
  Top Layer w12: J7.13@2621.85,700 2677.46,644.39 2909.39,644.39 2924.41,659.41 C42.1@2924.41,680 2927.32,682.91 R62.1@2927.32,760 2927.32,812.32 3305,1190 J10.4@3370,1190
HALLB: C43.1 J7.18 J10.3 R63.1 | length 941.6
  Top Layer w12: J7.18@2721.85,500 2756.85,465 2885,465 2924.41,504.41 C43.1@2924.41,530 2927.32,532.91 R63.1@2927.32,610 3310.47,993.15 J10.3@3370,993.15
HALLC: C44.1 J7.20 J10.2 R64.1 | length 938.7
  Top Layer w12: J7.20@2721.85,400 2801.85,320 2900,320 2924.41,344.41 C44.1@2924.41,370 2927.32,372.91 R64.1@2927.32,450 3273.62,796.3 J10.2@3370,796.3
INHA: J7.1 R5.1 R12.1 | length 1445.3
  Top Layer w7.87: v2(1775.29,920) R5.1@1775.29,967.44
  Top Layer w8: v2(1630,1085) 1636.11,1091.11 v2(1636.11,1145) R12.1@1636.11,1187.44
  Bottom Layer w7.87: v2(1636.11,1145) 1686.11,1195 2516.85,1195 J7.1@2621.85,1300
  Bottom Layer w8: v2(1630,1085) 1630,1035 1745,920 v2(1775.29,920)
INHB: J7.5 R7.1 R14.1 | length 1282.8
  Top Layer w8: v2(1566.52,1150) R14.1@1566.52,1187.44 ; v2(1670,1060) 1670,1003.14 R7.1@1705.7,967.44
  Bottom Layer w8: v2(1566.52,1150) 1601.52,1115 1650,1115 1670,1095 v2(1670,1060) 1765,1060 1795,1090 1829.17,1090 1839.17,1080 2555,1080 2575,1100 J7.5@2621.85,1100
INHC: J7.9 R2.1 R17.1 | length 1629.8
  Top Layer w7.87: 1530,905 1555,880 v2(1636.11,880) R2.1@1636.11,967.44
  Top Layer w8: R17.1@1496.93,1187.44 1496.93,1105 1530,1071.93 1530,905
  Bottom Layer w7.87: v2(1636.11,880) 1780,880 1821.93,921.93 1821.93,976.93 1870,1025 2496.85,1025 J7.9@2621.85,900
INLA: J7.3 R1.1 R13.1 | length 1318.4
  Top Layer w8: v2(1844.88,1115.12) R13.1@1844.88,1187.44 ; R1.1@1984.06,967.44 1984.06,940 2019.06,905 2105,905 2125,925 2125,1130 v2(2110,1145)
  Bottom Layer w8: v2(1844.88,1115.12) 1894.75,1165 2090,1165 v2(2110,1145) 2566.85,1145 J7.3@2621.85,1200
INLB: J7.7 R8.1 R15.1 | length 1096.7
  Top Layer w8: R15.1@1775.29,1187.44 1775.29,1099.71 1815,1060 v2(1810,1060) ; v2(1879.67,1055.42) v2@1880,1055.09 ; v2@1880,1060 v2@1880,1055.09 ; R8.1@1914.47,967.44 1880,1001.91 v2@1880,1055.09
  Bottom Layer w8: v2(1810,1060) 1875.09,1060 v2(1879.67,1055.42) 1884.25,1060 2561.85,1060 J7.7@2621.85,1000
INLC: J7.11 R3.1 R18.1 | length 1363.4
  Top Layer w7.87: R18.1@1705.7,1187.44 1705.7,1104.3 1737.76,1072.24 1737.76,902.24 1755,885 1820,885 1844.88,909.88 R3.1@1844.88,967.44 v2(1881.34,930.98)
  Bottom Layer w7.87: v2(1881.34,930.98) 1950.98,930.98 1995,975 2446.85,975 J7.11@2621.85,800
ISENA: C31.1 J6.16 R59.1 | length 167
  Top Layer w10: J6.16@1021.85,600 1079.41,542.44 C31.1@1110,542.44 R59.1@1165,542.44
LSS: C19.2 C20.2 C21.2 C25.2 C26.2 C27.2 J5.14 Q4.3 Q5.3 Q6.3 R55.1 R56.1 R57.1 R58.2 R60.2 TP3.1 U1.17 | length 2649.2
  Top Layer w7.87: R58.2@995,2322.56 R58.2@985,2322.56 982.44,2322.56 950.75,2354.25 950.75,2500.75 960,2510 R60.2@1033.58,2510 ; 1623.17,1664.86 1632.28,1655.75 U1.17@1760.2,1655.75
  Top Layer w25: 1480,1686.92 1494.92,1672 1616.03,1672 1623.17,1664.86
  Top Layer w50: C21.2@261.85,3411.65 261.85,3065.15 631.94,2695.06 1020,2695.06 ; J5.14@1345.67,2438.91 1345.67,2092.85 1388.52,2050 1388.52,1778.4 1480,1686.92
  other v1: 1183,2421 1258,2421 1145.5,2496 1220.5,2496 1295.5,2496 1445.5,2496 1670.5,2496 1745.5,2496 1895.5,2496 2120.5,2496 2195.5,2496 2345.5,2496 2570.5,2496 2645.5,2496 2720.5,2496 2795.5,2496 2870.5,2496 2945.5,2496 1183,2571 1258,2571 1558,2571 1633,2571 1708,2571 1783,2571 2008,2571 2083,2571 2158,2571 2233,2571 2308,2571 2533,2571 2683,2571 2758,2571 2833,2571 2908,2571 2983,2571 3058,2571 3133,2571 1520.5,2646 1595.5,2646 1670.5,2646 1745.5,2646 1895.5,2646 2120.5,2646 2195.5,2646 2270.5,2646 2345.5,2646 2495.5,2646 2720.5,2646 2795.5,2646 2870.5,2646 2945.5,2646 3020.5,2646 3095.5,2646 3170.5,2646 1483,2721 1558,2721 1633,2721 2233,2721 2308,2721 2383,2721 2458,2721 3208,2721 1145.5,2796 1220.5,2796 1295.5,2796 1370.5,2796 1445.5,2796 1520.5,2796 1595.5,2796 1670.5,2796 1745.5,2796 2195.5,2796 2270.5,2796 2345.5,2796 2420.5,2796 2495.5,2796 2570.5,2796 2795.5,2796 1108,2871 1183,2871 1258,2871 1333,2871 1408,2871 1483,2871 1558,2871 1633,2871 1708,2871 2158,2871 2233,2871 2308,2871 2383,2871 2458,2871 2533,2871 2608,2871 2758,2871 2833,2871 3133,2871 3208,2871 1070.5,2946 1145.5,2946 1220.5,2946 1295.5,2946 1370.5,2946 1445.5,2946 1820.5,2946 2120.5,2946 2195.5,2946 2270.5,2946 2345.5,2946 2420.5,2946 2495.5,2946 2795.5,2946 3095.5,2946 3170.5,2946 883,3021 958,3021 1108,3021 1183,3021 1258,3021 1333,3021 1408,3021 1783,3021 2008,3021 2158,3021 2233,3021 2308,3021 2383,3021 2458,3021 2533,3021 2758,3021 2833,3021 2983,3021 3058,3021 3208,3021 920.5,3096 1070.5,3096 1145.5,3096 1220.5,3096 1295.5,3096 1370.5,3096 1670.5,3096 1745.5,3096 1820.5,3096 1970.5,3096 2045.5,3096 2195.5,3096 2270.5,3096 2345.5,3096 2795.5,3096 3020.5,3096 3170.5,3096 733,3171 808,3171 883,3171 958,3171 1033,3171 1108,3171 1258,3171 1333,3171 1783,3171 1858,3171 1933,3171 2008,3171 2083,3171 2158,3171 2233,3171 2308,3171 2383,3171 2758,3171 2833,3171 2908,3171 2983,3171 3058,3171 3133,3171 3208,3171 1145.5,3246 1295.5,3246 1595.5,3246 2345.5,3246 2645.5,3246 1258,3321 1333,3321 2383,3321
MCU_LED: J7.4 R25.1 | length 1927.9
  Top Layer w12: R25.1@1132.56,1600 1232.44,1600 v2(1233.78,1598.66)
  Bottom Layer w12: v2(1233.78,1598.66) 1235,1598.66 1608.66,1225 2360,1225 2510,1375 2630,1375 2670,1335 2670,1270 2721.85,1218.15 J7.4@2721.85,1200
NC_MCU/POT_49C: J6.14 R39.2 | length 424.1
  Bottom Layer w10: J6.14@1021.85,700 1080,700 1145,635 1335,635 1375,595 R39.2@1375,567.56
NetC2_1: C2.1 C35.1 J16.1 U3.1 | length 434.5
  Top Layer w12: C35.1@2855,2115.35 2856.97,2113.39 U3.1@2942.4,2113.39
  Top Layer w25: J16.1@2656.37,1932.76 2656.37,2053.01 2720.69,2117.32 C2.1@2785,2117.32 2786.97,2115.35 C35.1@2855,2115.35
NetC10_2: C10.2 R40.2 | length 152.4
  Top Layer w39.37: R40.2@2863.43,4103.85 2863.43,3970.75 C10.2@2877.09,3957.09
NetC11_2: C11.2 R41.2 | length 146.2
  Top Layer w39.37: R41.2@1862.09,4100 1862.09,3957.91 C11.2@1865,3955
NetC12_2: C12.2 R42.2 | length 158.8
  Top Layer w39.37: C12.2@795,3942.09 797.09,3944.17 R42.2@797.09,4100
NetC22_2: C22.2 R56.2 | length 109.9
  Top Layer w39.37: R56.2@2275,3357.97 C22.2@2275,3467.91
NetC23_2: C23.2 R57.2 | length 125.8
  Top Layer w39.37: R57.2@1205,3277.09 C23.2@1205,3402.91
NetC24_2: C24.2 R55.2 | length 120.8
  Top Layer w39.37: R55.2@3285,3352.09 C24.2@3285,3472.91
NetC37_1: C37.1 U3.7 | length 73.5
  Top Layer w12: U3.7@3117.6,2087.8 3120.46,2090.65 3144.73,2090.65 3156.64,2102.56 C37.1@3185,2102.56
NetC49_1: C49.1
NetC49_2: C49.2
NetD1_1: D1.1 J1.1 | length 180
  Top Layer w20: J1.1@730,1925 D1.1@910,1925
NetD1_2: D1.2 R22.2 | length 84.8
  Top Layer w20: D1.2@992.68,1925 R22.2@1077.44,1925
NetD2_1: D2.1 J2.1 | length 182.3
  Top Layer w20: J2.1@730,1759.41 904.41,1759.41 D2.1@910,1765
NetD2_2: D2.2 R23.2 | length 84.8
  Top Layer w20: D2.2@992.68,1765 R23.2@1077.44,1765
NetD3_1: D3.1 J3.1 | length 130.2
  Top Layer w39.37: D3.1@763.62,4375 886.77,4375 J3.1@891.77,4380
NetD3_2: D3.2 R24.2 | length 84.1
  Top Layer w19.68: R24.2@661,4449.88 683.31,4427.58 D3.2@683.31,4375
NetD4_1: D4.1 J4.1 | length 180.7
  Top Layer w20: J4.1@730,1595 903.66,1595 D4.1@908.66,1600
NetD4_2: D4.2 R25.2 | length 86.1
  Top Layer w12: D4.2@991.34,1600 R25.2@1077.44,1600
NetD5_1: D5.1 R46.2 | length 84.2
  Top Layer w20: D5.1@2421.3,3172.13 2435.08,3158.35 R46.2@2435.08,3093.66
NetD6_1: D6.1 R47.2 | length 89.6
  Top Layer w20: D6.1@1403.58,3162.28 1403.58,3077.5 R47.2@1406.95,3074.13
NetD7_1: D7.1 R48.2 | length 106.8
  Top Layer w20: D7.1@340.59,3205.59 358.93,3187.25 R48.2@358.93,3106.39
NetD8_1: D8.1 R52.2 | length 84.9
  Top Layer w20: D8.1@2871.69,2895 2871.69,2814.8 R52.2@2875,2811.5
NetD9_1: D9.1 R53.2 | length 91
  Top Layer w20: R53.2@1845,2810 1847.49,2812.49 D9.1@1847.49,2900
NetD10_1: D10.1 R54.2 | length 93.3
  Top Layer w20: D10.1@798.27,2919.83 813.03,2905.07 R54.2@813.03,2832.62
NetH1_1: H1.1
NetH2_1: H2.1
NetH3_1: H3.1
NetH4_1: H4.1
NetJ6_2: J6.2 R30.1 | length 110.6
  Bottom Layer w10: J6.2@1021.85,1300 R30.1@1132.44,1300
NetJ6_5: J6.5
NetJ6_7: J6.7
NetJ6_13: J6.13
NetJ6_15: J6.15 R35.2 | length 233.7
  Top Layer w12: J6.15@921.85,600 925.24,600 975.24,650 1092.44,650 R35.2@1122.44,680
NetJ6_17: J6.17
NetJ6_18: J6.18
NetJ6_19: J6.19
NetJ7_8: J7.8
NetJ7_10: J7.10
NetJ7_12: J7.12
NetJ7_14: J7.14
NetJ7_17: J7.17
NetJ8_1: J8.1 U3.5 | length 286.1
  Top Layer w12: U3.5@3117.6,2036.61 3117.6,2022.4 3135,2005 3205,2005 3295,2095 J8.1@3295,2145
NetJ11_1: J11.1 TP31.1 | length 161.6
  Top Layer w50: TP31.1@3410,1725 3410,1685 3450,1645 J11.1@3450,1580
NetJ13_1: J13.1 R87.2 | length 1224.7
  Top Layer w25: v2(2350,1610) 2350,1638.64 2356.76,1645.4 R87.2@2356.76,1694.35
  Power Layer w25: J13.1@2030,605 2210,785 2210,1470 v2(2350,1610)
NetJ14_1: J14.1 R88.2 | length 282.3
  Top Layer w12: J14.1@3295,1955 3470,2130 R88.2@3504.8,2130
NetJ15_1: J15.1 R92.2 | length 467.3
  Top Layer w20: J15.1@2035,410 2113.35,410 R92.2@2388.35,135
NetJ15_3: J15.3 TP30.1 | length 185.4
  Top Layer w20: TP30.1@1660,385 1735.2,385 1760.2,410 J15.3@1835,410
NetR37_2: R37.2 R76.2 | length 73.4
  Top Layer w12: R76.2@1165.83,347.4 R37.2@1239.25,347.4
NetR73_1: R73.1 S1.3 | length 393.6
  Bottom Layer w12: S1.3@193.7,745.28 193.7,838.7 250,895 250,1042.44 R73.1@200,1092.44
  Bottom Layer w25: R73.1@200,1090 R73.1@200,1092.44
NetR74_1: R74.1 S2.1 | length 151.6
  Bottom Layer w20: S2.1@785,194.37 855.34,264.71 R74.1@907.44,264.71
NetR78_2: R78.2 R81.1 R82.2 R84.2 | length 279
  Bottom Layer w20: R84.2@477.38,1742.3 R82.2@477.38,1649.36 R78.2@477.38,1552.3 477.38,1517.62 493.58,1501.42 R81.1@493.58,1470
NetR80_2: R80.2 S2.3 | length 201.7
  Bottom Layer w12: R80.2@496.85,357.01 496.85,278.15 580.63,194.37 S2.3@585,194.37
NetR81_2: R81.2 R83.2 | length 99.9
  Bottom Layer w20: R81.2@548.7,1470 642.65,1470 R83.2@646.85,1465.8
NetR83_1: R83.1 R85.1 R86.2 | length 188.7
  Bottom Layer w20: R86.2@549.41,1405.72 554.36,1410.68 R83.1@646.85,1410.68 729.93,1410.68 R85.1@734.29,1406.31
NetR88_3: R88.3
NetR89_1: R89.1 R92.1 | length 374.1
  Top Layer w20: R89.1@2146.85,123.5 2180.4,89.95 2443.3,89.95 R92.1@2488.35,135
NetS1_1: S1.1
NetU1_20: 
NetU1_21: 
NetU1_22: 
NetU3_2: U3.2
NetU3_3: U3.3
nFAULT: R9.1 R16.2 R19.1 R23.1 R31.1 R33.1 TP4.1 | length 2765.5
  Top Layer w8: v2(1420,850) 1862.44,850 1942.44,930 ; R33.1@1905.11,810.58 1942.44,847.9 ; R19.1@1914.47,1187.44 1914.47,1115.53 1945,1085 1945,930 1942.44,930 ; R31.1@2027.69,805.11 2025.54,807.26 R31.1@2022.44,807.26 ; R9.1@2120.5,1187.44 R16.2@2192.44,1115.5 ; TP4.1@2280,1215 2280,1203.06 R16.2@2192.44,1115.5 ; 1942.44,847.9 1943.32,847.9 1983.97,807.26 R31.1@2022.44,807.26 ; 1942.44,847.9 1942.44,930 ; R31.1@2022.44,807.26 2060.18,845 2086.68,845 2145,903.32 2145,1067.56 R16.2@2192.44,1115 R16.2@2192.44,1115.5
  Top Layer w10: R23.1@1132.56,1765 1190,1765 1270,1685 v2(1270,1000)
  Bottom Layer w8: v2(1270,1000) v2(1420,850)
nFAULT_49C: R31.2 R38.1 | length 595.6
  Top Layer w8: R31.2@2077.56,807.26 v2(2131.95,807.26)
  Bottom Layer w8: v2(2131.95,807.26) 2467.44,471.76 R38.1@2467.44,405
nFAULT_49C/CSAREF: J7.19 R36.2 R38.2 | length 162.1
  Bottom Layer w8: R36.2@2520.83,345 2522.56,346.73 R38.2@2522.56,405 2616.85,405 J7.19@2621.85,400
nFAULT_DFLT: J7.6 R33.2 R35.1 | length 1923.5
  Top Layer w8: R35.1@1177.56,680 1201.47,680 1215.59,694.12 v2(1220,694.12) ; v2(1356.8,695) 1721.88,695 1831.98,805.11 R33.2@1847.34,805.11 ; R33.2@1854.26,805.11 R33.2@1847.34,805.11 ; J7.6@2721.85,1100 2671.85,1150 2606.26,1150 2548.7,1092.44 2311.2,1092.44 2278.76,1060 2204.58,1060 2180,1035.42 2180,818.07 2131.93,770 1882.45,770 R33.2@1847.34,805.11
  Bottom Layer w8: v2(1220,694.12) 1220,695 v2(1356.8,695)
nSLEEP: D11.1 R10.1 R11.1 R26.1 R27.1 R75.2 TP2.1 | length 2654
  Top Layer w7.87: R27.1@1544.49,803.25 1583.25,803.25 v2(1600,820) 1615,805 R26.1@1667.95,805 ; R11.1@1984.06,1187.44 1984.06,1118.94 2020,1083 2020,1001.09 R10.1@2053.65,967.44 2026.2,940 v2(2025,940)
  Top Layer w12: v2(1180,815) TP2.1@1180,895 ; v2(1323.85,586.53) 1323.85,720.63 1368.22,765 1506.24,765 R27.1@1544.49,803.25
  Bottom Layer w7.87: 1345,820 v2(1600,820) 1775,820 1840,885 1970,885 v2(2025,940)
  Bottom Layer w8: v2(1180,815) 1185,820 1345,820
  Bottom Layer w12: R75.2@486.85,588.66 566.22,588.66 D11.1@568.19,586.69 873.62,586.69 903.83,556.49 1039.87,556.49 1069.92,586.53 v2(1323.85,586.53)
nSLEEP_49C: J7.15 R26.2 | length 1005.9
  Top Layer w8: R26.2@1723.07,805 1723.07,768.34 v2(1725,766.41) ; v2(1834.14,740) 1835,740.86 2480.99,740.86 J7.15@2621.85,600
  Bottom Layer w8: v2(1725,766.41) 1751.41,740 v2(1834.14,740)
nSLEEP_DFLT: J6.9 R27.2 | length 710.3
  Top Layer w7.87: J6.9@907.44,900 J6.9@921.85,900 967.97,853.88 967.97,778.45 996.41,750 1124.29,750 1153.86,779.57 v2(1237.4,779.57) ; v2(1345,795) 1353.25,803.25 R27.2@1489.37,803.25
  Bottom Layer w7.87: v2(1237.4,779.57) 1329.57,779.57 v2(1345,795)
nSLEEP_SW: C36.1 R75.1 R77.2 S1.2 TP23.1 | length 517
  Top Layer w12: S1.2@193.7,645.28 416.57,645.28 TP23.1@416.85,645
  Bottom Layer w12: R75.1@485.36,645.28 R75.1@486.85,643.78
  Bottom Layer w20: S1.2@193.7,645.28 R75.1@485.36,645.28
OUTA: C10.1 C13.2 C24.1 J12.1 NT1.2 Q1.3 Q4.4 R67.2 R78.1 TP34.1 | length 7000.1
  Top Layer w20: v2(345,1552.3) 345,1468.88 450.43,1363.44 450.43,1268.69 516.57,1202.56 R67.2@676.39,1202.56
  Top Layer w50: 2619.68,3323.5 2700,3323.5 2784.46,3323.5
  Bottom Layer w20: R78.1@418.32,1552.3 v2(345,1552.3) 327.7,1552.3 100,1780 100,4610 200,4710 395,4710 653.78,4968.78 653.78,5033.78 705,5085 2495,5085 2536.61,5043.39 J12.1@2536.61,4720
  other v1: 2833,4221 2908,4221 2983,4221 3058,4221 3133,4221 2645.5,4296 2945.5,4296 3020.5,4296 2533,4371 2608,4371 2908,4371 2983,4371 2495.5,4446 2570.5,4446 2645.5,4446 2720.5,4446 2795.5,4446 2870.5,4446 2458,4521 2533,4521 2608,4521 2683,4521 2758,4521 2833,4521 2495.5,4596 2570.5,4596 2645.5,4596 2720.5,4596 2458,4671 2608,4671 2683,4671 2645.5,4746 2720.5,4746 2458,4821 2533,4821 2608,4821 2683,4821
OUTB: C11.1 C15.2 C22.1 J12.2 NT2.2 Q2.3 Q5.4 R68.2 R82.1 TP35.1 | length 6817
  Top Layer w20: v2(240,1710) 240,1535.69 423.43,1352.26 423.43,1208.38 544.25,1087.56 674.32,1087.56 R68.2@676.39,1085.49 ; NT2.2@1704.76,3324.33 NT2.2@1715.47,3324.33
  Top Layer w50: 1613.18,3324.33 NT2.2@1704.76,3324.33 ; NT2.2@1715.47,3324.33 1808.12,3324.33 1792.75,3339.7
  Bottom Layer w20: R82.1@418.32,1649.36 300.64,1649.36 v2(240,1710) 127.87,1822.13 127.87,4598.45 211.55,4682.13 406.55,4682.13 681.65,4957.23 681.65,5022.23 716.55,5057.13 2130,5057.13 2161.8,5025.32 J12.2@2161.8,4720
  other v1: 1858,4296 1933,4296 2008,4296 2308,4296 2383,4296 2458,4296 1895.5,4371 1970.5,4371 2045.5,4371 2270.5,4371 2345.5,4371 2420.5,4371 2008,4446 2083,4446 2158,4446 2233,4446 2308,4446 2383,4446 2045.5,4521 2120.5,4521 2195.5,4521 2270.5,4521 2345.5,4521 2008,4596 2083,4596 2158,4596 2233,4596 2308,4596 2045.5,4671 2120.5,4671 2195.5,4671 2270.5,4671 2345.5,4671 2008,4746 2083,4746 2233,4746 2308,4746 2045.5,4821 2120.5,4821 2195.5,4821 2270.5,4821 2345.5,4821
OUTC: C12.1 C17.2 C23.1 J12.3 NT3.2 Q3.3 Q6.4 R69.2 R84.1 TP36.1 | length 6354.6
  Top Layer w20: v2(180,1860) 180,1535 396.43,1318.57 396.43,1073.75 501.76,968.42 R69.2@676.39,968.42
  Bottom Layer w20: R84.1@418.32,1742.3 297.7,1742.3 v2(180,1860) 160.16,1879.84 160.16,3726.12 165,3730.96 165,4597.4 222.73,4655.13 417.73,4655.13 710,4947.4 710,5008.45 726.55,5025 1740.09,5025 1744.09,5029 1787,4986.09 J12.3@1787,4720
  other v1: 1183,4296 1258,4296 1333,4296 1408,4296 1633,4296 1708,4296 1295.5,4371 1370.5,4371 1670.5,4371 1745.5,4371 1333,4446 1408,4446 1483,4446 1558,4446 1633,4446 1708,4446 1783,4446 1858,4446 1445.5,4521 1520.5,4521 1595.5,4521 1670.5,4521 1745.5,4521 1820.5,4521 1895.5,4521 1483,4596 1558,4596 1633,4596 1708,4596 1783,4596 1858,4596 1595.5,4671 1670.5,4671 1745.5,4671 1820.5,4671 1895.5,4671 1633,4746 1708,4746 1858,4746 1745.5,4821 1820.5,4821 1895.5,4821
P18: R6.2 R17.2 U1.18 | length 887.9
  Top Layer w8: R6.2@1496.93,1022.56 1496.93,1068.07 1460,1105 1460,1205.63 R17.2@1496.93,1242.56 1496.93,1600 1536.93,1640 U1.18@1760.2,1640
P19: C1.2 R4.2 R14.2 U1.19 | length 836.7
  Top Layer w8: R4.2@1566.52,1022.56 1566.52,1069.48 1535,1101 1535,1211.04 R14.2@1566.52,1242.56 1525,1284.08 1525,1550 1579.57,1604.57 C1.2@1610,1604.57 1662.13,1604.57 1681.81,1624.25 U1.19@1760.2,1624.25
P20: R2.2 R12.2 U1.20 | length 690.7
  Top Layer w8: R2.2@1636.11,1022.56 1636.11,1035.82 1595.5,1076.43 1595.5,1201.95 R12.2@1636.11,1242.56 1636.11,1518.12 1726.5,1608.5 U1.20@1760.2,1608.5
P21: R7.2 R18.2 U1.21 | length 631.3
  Top Layer w8: R7.2@1705.7,1022.56 1705.7,1049.29 1705.63,1049.36 1705.63,1075.06 1675,1105.7 1675,1211.86 R18.2@1705.7,1242.56 1705.7,1560.7 1737.76,1592.76 U1.21@1760.2,1592.76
